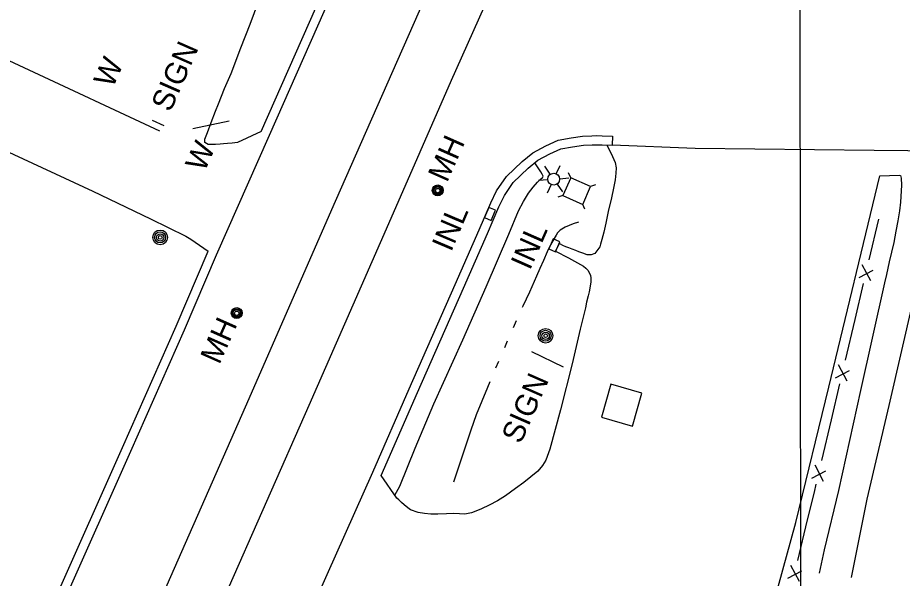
# Model space of a CAD drawing. Extents: x 189384 to 193282, y 256970 to 260388.
# Drawn here: x 190431.5 to 190675.6, y 257840.1 to 257994.7 of the extents above; entities that cross this region are included whole.
import ezdxf

# ---------------------------------------------------------------- set-up
doc = ezdxf.new("R2010")
doc.units = 0
for name, color, linetype in [('E_DRN_Grate', 7, 'Continuous'), ('E_DWY', 7, 'Continuous'), ('E_MAP_GridLines', 7, 'Continuous'), ('E_MISCPROP', 7, 'Continuous'), ('E_MISCPROP_HvyLine', 7, 'Continuous'), ('E_MISCPROP_Railing', 7, 'Continuous'), ('E_PATH_Sidewalk', 7, 'Continuous'), ('E_RDWY', 7, 'Continuous'), ('E_UTL_AboveGroundPipe', 7, 'Continuous'), ('E_WTR', 7, 'Continuous')]:
    doc.layers.add(name, color=color, linetype=linetype)

# ---------------------------------------------------------------- blocks, each defined once
blk = doc.blocks.new('WAL_1')
at = {"layer": 'E_MISCPROP_Railing'}
blk.add_text('W', height=6, rotation=0.0001, dxfattribs=at).set_placement((-2.3, -3.01))
blk = doc.blocks.new('WAL_3')
at = {"layer": 'E_MISCPROP_Railing'}
blk.add_text('W', height=6, rotation=359.9999, dxfattribs=at).set_placement((-2.27, -3.34))
blk = doc.blocks.new('INLT_1')
at = {"layer": 'E_MISCPROP_Railing'}
blk.add_lwpolyline([(3, -2), (3, 0), (0, 0), (0, -2), (3, -2)], dxfattribs=at)
blk = doc.blocks.new('INL_1')
at = {"layer": 'E_MISCPROP_Railing'}
blk.add_text('INL', height=6, rotation=359.9999, dxfattribs=at).set_placement((-5.79, -2.75))
blk = doc.blocks.new('INLT')
at = {"layer": 'E_MISCPROP_Railing'}
blk.add_lwpolyline([(3, -2), (3, 0), (0, 0), (0, -2), (3, -2)], dxfattribs=at)
blk = doc.blocks.new('INL_2')
at = {"layer": 'E_MISCPROP_Railing'}
blk.add_text('INL', height=6, rotation=359.9999, dxfattribs=at).set_placement((-5.79, -2.75))
blk = doc.blocks.new('POLE_2')
at = {"layer": 'E_MISCPROP'}
for centre, radius in [((-0.01, 0.02), 2.02), ((-0.01, 0.03), 1.52), ((0, -0.01), 1.01), ((0, 0), 0.502)]:
    blk.add_circle(centre, radius, dxfattribs=at)
blk = doc.blocks.new('SIGN_1')
at = {"layer": 'E_MISCPROP'}
blk.add_text('SIGN', height=6, rotation=360, dxfattribs=at).set_placement((-9.61, -3.01))
blk = doc.blocks.new('PED')
at = {"layer": 'E_UTL_AboveGroundPipe'}
for p, q in [((-2.34, 2.71), (-3.29, 3.77)), ((3.06, 2.71), (4.02, 3.77)), ((-3.29, -4.35), (-2.34, -3.29)), ((4.02, -4.35), (3.06, -3.29))]:
    blk.add_line(p, q, dxfattribs=at)
blk.add_lwpolyline([(-2.34, -3.29), (3.06, -3.29), (3.06, 2.71), (-2.34, 2.71)], close=True, dxfattribs=at)
blk = doc.blocks.new('LTP_5')
at = {"layer": 'E_MISCPROP'}
for p, q in [((-0.8, 1.43), (-2, 3.73)), ((0.9, 1.42), (2.27, 3.65)), ((-1.63, 0.07), (-4.24, 0.14)), ((-0.88, -1.42), (-2.24, -3.61)), ((0.76, -1.47), (2, -3.65)), ((1.64, -0.02), (4.16, -0.09))]:
    blk.add_line(p, q, dxfattribs=at)
blk.add_circle((0, 0), 1.64, dxfattribs=at)
blk = doc.blocks.new('MHO')
at = {"layer": 'E_DRN_Grate'}
for centre, radius in [((0.04, -0.06), 1.5), ((0.04, -0.06), 1.22), ((0.04, -0.07), 0.968), ((0.01, -0.08), 0.605)]:
    blk.add_circle(centre, radius, dxfattribs=at)

msp = doc.modelspace()

# ---------------------------------------------------------------- linework, layer by layer
at = {"layer": 'E_DWY'}
for points in [[(190498.7, 257963.32), (190492.15, 257960.32), (190490.67, 257960.12), (190489.42, 257959.97), (190488.25, 257959.89), (190487.37, 257959.85), (190486.1, 257959.77), (190485.24, 257959.73), (190484.03, 257959.75), (190483.1, 257960.32), (190483.15, 257961.19), (190483.82, 257963.04), (190484.92, 257965.76), (190486.1, 257968.91), (190486.92, 257970.97), (190488.6, 257975.15), (190490.36, 257979.32), (190493.06, 257986.35), (190495.6, 257992.94), (190498.03, 257999.34)], [(190594.08, 257959.61), (190595.57, 257956.39), (190596.34, 257954.79), (190596.64, 257953.32), (190596.56, 257951.81), (190596.31, 257949.96), (190595.84, 257947.71), (190595.29, 257945.02), (190594.42, 257941.22), (190593.74, 257938.05), (190593.2, 257935.51), (190592.67, 257933.56), (190592.3, 257932.23), (190592.06, 257931.48), (190590.74, 257929.63), (190589.72, 257929.28), (190588.59, 257929.32), (190587.41, 257929.78), (190586.35, 257930.16), (190585.44, 257930.52), (190584.51, 257930.88), (190583.57, 257931.19), (190582.77, 257931.51), (190581.86, 257931.9), (190581.25, 257932.25), (190580.87, 257932.43), (190579.92, 257930.28), (190579.92, 257930.28), (190583.48, 257928.5), (190587.62, 257926.16), (190588.2, 257925.65), (190588.75, 257925.09), (190589.5, 257923.7), (190589.63, 257922.84), (190589.58, 257921.87), (190589.43, 257920.65), (190589.12, 257919.13), (190588.87, 257917.97), (190588.46, 257916.19), (190588.11, 257914.67), (190586.66, 257908.77), (190584.48, 257899.2), (190581.25, 257886.57), (190578.28, 257875.71), (190577.17, 257872.68), (190576.33, 257871.17), (190574.99, 257869.61), (190573.08, 257868.06), (190571.1, 257866.45), (190568.86, 257864.85), (190566.06, 257862.82), (190563.89, 257861.43), (190561.54, 257860.2), (190559.49, 257859.26), (190557.89, 257858.59), (190556.72, 257858.16), (190554.83, 257857.78), (190553.42, 257857.81), (190551.75, 257857.9), (190549.76, 257857.81), (190547.38, 257857.75), (190545.5, 257857.75), (190543.7, 257857.95), (190541.97, 257858.26), (190539.86, 257858.97), (190539.09, 257859.49), (190538.12, 257860.34), (190537.4, 257861.01), (190536.61, 257861.73), (190536.12, 257862.2), (190531.78, 257868.41)], [(190427.9, 257958.16), (190452.19, 257946.89), (190468.17, 257939.18), (190477.91, 257934.41), (190479.24, 257933.63), (190484.04, 257930.29)], [(190661.52, 257840.27), (190665.86, 257861.86), (190671.96, 257887.76), (190678.6, 257916.85), (190682.96, 257941.54), (190683.86, 257945.03), (190684.34, 257946.55), (190684.86, 257947.8), (190685.25, 257948.61), (190685.63, 257949.24), (190686.06, 257949.8), (190686.5, 257950.36), (190687.19, 257951.23), (190694.29, 257951.04), (190695.6, 257957.83)], [(190641.31, 257837.75), (190646.22, 257855.42), (190655.24, 257892.8), (190669.35, 257951.05), (190674.66, 257951.28), (190675.05, 257951.21), (190675.25, 257950.41), (190675.32, 257948.48), (190675.06, 257943.85), (190674.75, 257941.39), (190674.32, 257938.69), (190673.77, 257935.86), (190673.19, 257932.66), (190671.89, 257927.37), (190671.15, 257923.88), (190670.65, 257921.58), (190664.04, 257891.89), (190657.92, 257864.25), (190654.04, 257847.93), (190652.64, 257841.47)]]:
    msp.add_lwpolyline(points, dxfattribs=at)
at = {"layer": 'E_MAP_GridLines'}
for p, q in [((190647.76, 257511.45), (190646.69, 259011.44)), ((190648.11, 257011.45), (190647.05, 258511.45))]:
    msp.add_line(p, q, dxfattribs=at)
at = {"layer": 'E_MISCPROP'}
for p, q in [((190471.87, 257964.88), (190468.69, 257966.38)), ((190582.07, 257898.29), (190573.36, 257902.52))]:
    msp.add_line(p, q, dxfattribs=at)
at = {"layer": 'E_MISCPROP_HvyLine'}
msp.add_lwpolyline([(190601.1, 257882.07), (190603.73, 257891.16), (190595.18, 257893.62), (190592.56, 257884.53)], close=True, dxfattribs=at)
at = {"layer": 'E_MISCPROP_Railing'}
for p, q in [((190663.68, 257923.05), (190667.49, 257925.09)), ((190666.86, 257922.13), (190664.52, 257926.57)), ((190660.34, 257894.46), (190657.99, 257898.91)), ((190657.16, 257895.38), (190660.96, 257897.42)), ((190653.81, 257866.79), (190651.47, 257871.24)), ((190650.64, 257867.71), (190654.44, 257869.75)), ((190643.99, 257840.09), (190647.8, 257842.1)), ((190647.16, 257839.14), (190644.84, 257843.6))]:
    msp.add_line(p, q, dxfattribs=at)
for points in [[(190367.73, 258011.21), (190393.44, 257999.47), (190433.18, 257980.95), (190470.64, 257963.5)], [(190489.81, 257966.17), (190479.83, 257964.09)], [(190666.4, 257927.92), (190669.06, 257939.16)], [(190662.53, 257911.49), (190664.86, 257921.38)], [(190659.88, 257900.25), (190662.53, 257911.49)], [(190656.01, 257883.82), (190658.34, 257893.71)], [(190653.36, 257872.58), (190656.01, 257883.82)], [(190649.44, 257856.16), (190651.3, 257863.85), (190651.82, 257866.04)], [(190646.73, 257844.94), (190649.44, 257856.16)]]:
    msp.add_lwpolyline(points, dxfattribs=at)
at = {"layer": 'E_PATH_Sidewalk'}
msp.add_lwpolyline([(190535.58, 257862.97), (190536.91, 257865.5), (190541.15, 257875.95), (190546.28, 257888.2), (190554.33, 257905.88), (190560.76, 257920.42), (190567.04, 257935.01), (190569.66, 257941.45), (190571.03, 257943.99), (190572.44, 257946.27), (190573.67, 257947.92), (190574.9, 257949.35), (190575.54, 257949.94), (190576.27, 257950.61), (190576.37, 257950.74), (190576.43, 257951.03), (190576.23, 257951.51), (190575.82, 257952.16), (190574.18, 257954.69)], dxfattribs=at)
at = {"layer": 'E_RDWY'}
for points in [[(190486.34, 257929.3), (190500.99, 257962.31), (190519.93, 258005.2), (190540.88, 258052.68), (190557.27, 258090.57), (190575.92, 258132.39), (190589.56, 258163.44), (190602.68, 258193.06), (190616.68, 258225.7)], [(190498.7, 257963.32), (190517.65, 258006.21), (190538.59, 258053.68), (190554.98, 258091.58), (190573.63, 258133.41), (190587.27, 258164.44), (190600.39, 258194.06), (190614.38, 258226.68)], [(190639.31, 258218.07), (190609.41, 258149.39), (190580.27, 258083.06), (190547.78, 258009.13), (190519.09, 257944.03), (190494.25, 257887.28), (190465.55, 257822.08), (190442.19, 257769.07), (190419.9, 257718.5), (190394.49, 257660.93), (190374.24, 257614.8), (190349, 257556.99), (190323.12, 257498.57), (190298.43, 257442.39), (190276.94, 257393.85), (190259.86, 257355.22)], [(190647.06, 258194.52), (190624.13, 258142.92), (190594.92, 258076.29), (190570.69, 258021.28), (190551.11, 257977.35), (190533.78, 257937.86), (190511.8, 257887.72), (190488.43, 257834.81), (190463.86, 257779), (190437.37, 257718.32), (190410.84, 257658.32), (190384.1, 257597.28), (190367.03, 257558.94), (190342.84, 257503.57), (190317.05, 257445.11), (190294.43, 257394.4)], [(190516.9, 257841.07), (190529.47, 257869.38), (190539.54, 257892.33), (190552.18, 257921.07), (190558.86, 257936.22), (190561.99, 257943.6), (190563.6, 257946.92), (190566.33, 257950.89), (190570.67, 257955.05), (190573.6, 257957.46), (190577.25, 257959.4), (190580.61, 257960.91), (190584.19, 257961.6), (190587.36, 257962.02), (190589.88, 257962.14), (190591.27, 257962.18), (190592.78, 257962.16), (190595.58, 257962.06), (190595.49, 257959.56)], [(190531.76, 257868.38), (190541.83, 257891.33), (190554.46, 257920.07), (190561.15, 257935.22), (190564.27, 257942.56), (190565.77, 257945.66), (190568.24, 257949.26), (190572.33, 257953.17), (190574.99, 257955.37), (190578.35, 257957.15), (190581.37, 257958.52), (190584.59, 257959.13), (190587.58, 257959.53), (190589.98, 257959.64), (190591.29, 257959.68), (190592.72, 257959.66), (190595.49, 257959.56)], [(190595.49, 257959.66), (190618.38, 257958.74), (190667.75, 257958.12), (190695.6, 257957.93)], [(190250.08, 257392.44), (190265, 257426.05), (190280.63, 257461.47), (190298.01, 257501.1), (190315.61, 257540.66), (190329.32, 257571.82), (190346.52, 257610.97), (190369.12, 257662.7), (190389.76, 257709.75), (190408.17, 257751.62), (190431.5, 257804.24), (190444.63, 257834.42), (190462.73, 257875.09), (190477.51, 257908.64), (190486.34, 257929.3)], [(190262.71, 257427.06), (190278.34, 257462.48), (190295.73, 257502.11), (190313.33, 257541.67), (190327.03, 257572.83), (190344.23, 257611.97), (190366.83, 257663.7), (190387.47, 257710.75), (190405.88, 257752.63), (190429.21, 257805.24), (190442.34, 257835.43), (190460.44, 257876.1), (190475.22, 257909.64), (190484.04, 257930.29)], [(190495.68, 257792.62), (190507.25, 257819.11), (190510.8, 257827.52), (190516.9, 257841.07)]]:
    msp.add_lwpolyline(points, dxfattribs=at)
at = {"layer": 'E_WTR'}
for points in [[(190586.24, 257938.3), (190584.76, 257937.8), (190582.53, 257936.9), (190581.19, 257936.11), (190580.41, 257935.34), (190580.06, 257934.75), (190579.78, 257934.23), (190578.5, 257932.02), (190578.15, 257931.31), (190577.61, 257930.14), (190576.52, 257927.7), (190575.54, 257925.51), (190574.6, 257923.39), (190572.72, 257919.01), (190570.86, 257915.1), (190570.7, 257914.75)], [(190569.02, 257911.06), (190568.2, 257909.2)], [(190566.58, 257905.47), (190565.78, 257903.6)], [(190564.16, 257899.87), (190563.36, 257898)], [(190561.74, 257894.27), (190561.07, 257892.71), (190559.58, 257888.97), (190558.01, 257885.12), (190556.5, 257880.89), (190551.73, 257866.56)]]:
    msp.add_lwpolyline(points, dxfattribs=at)

# ---------------------------------------------------------------- block references
at = {"layer": 'E_DRN_Grate'}
for p, rotation in [((190547.3, 257947.05), 66.02694868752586), ((190491.86, 257913.21), 66.02694967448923)]:
    msp.add_blockref('MHO', p, dxfattribs=dict(at, rotation=rotation))
at = {"layer": 'E_MISCPROP'}
for name, p, rotation in [('SIGN_1', (190474.73, 257978.43), 66.26477281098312), ('LTP_5', (190579.38, 257950.17), 66.2647709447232), ('POLE_2', (190470.83, 257934.1), 66.26477287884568), ('POLE_2', (190577.15, 257906.97), 66.26477098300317), ('SIGN_1', (190571.38, 257886.9), 66.26477108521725)]:
    msp.add_blockref(name, p, dxfattribs=dict(at, rotation=rotation))
at = {"layer": 'E_MISCPROP_Railing'}
for name, p, rotation in [('WAL_1', (190455.89, 257978.38), 66.07484530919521), ('WAL_3', (190480.88, 257955.34), 66.07484486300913)]:
    msp.add_blockref(name, p, dxfattribs=dict(at, rotation=rotation))
for name, p, xscale, yscale, rotation in [('INL_1', (190550.81, 257936.3), 0.9999971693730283, 0.9999971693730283, 66.98954850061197), ('INLT_1', (190560.29, 257939.59), 0.9999971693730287, 0.9999971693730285, 66.98954833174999), ('INL_2', (190572.62, 257931.23), 0.9999980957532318, 0.9999980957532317, 66.20874903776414), ('INLT', (190578.03, 257930.94), 0.9999980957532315, 0.9999980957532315, 66.2087489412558)]:
    msp.add_blockref(name, p, dxfattribs=dict(at, xscale=xscale, yscale=yscale, rotation=rotation))
at = {"layer": 'E_UTL_AboveGroundPipe', "rotation": 66.26477083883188}
msp.add_blockref('PED', (190585.32, 257946.68), dxfattribs=at)

# ---------------------------------------------------------------- texts
at = {"layer": 'E_DRN_Grate'}
for p in [(190549.95, 257949.03), (190487.14, 257898.81)]:
    msp.add_text('MH', height=6, rotation=66.027, dxfattribs=at).set_placement(p)

doc.saveas('drawing.dxf')
